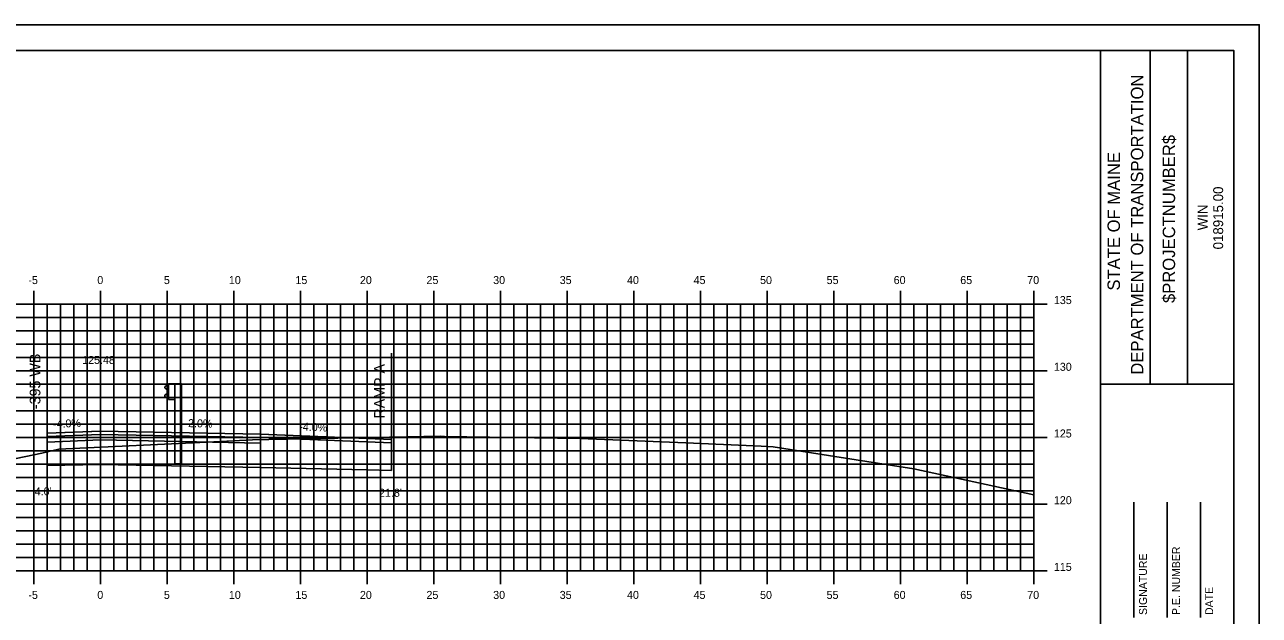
# Model space of a CAD drawing. Extents: x 851960 to 852132, y 365624 to 365734.
# Drawn here: x 852037.6 to 852130.2, y 365689.7 to 365734 of the extents above; entities that cross this region are included whole.
import ezdxf

# ---------------------------------------------------------------- set-up
doc = ezdxf.new("R2010")
doc.units = 0
for name, color, linetype in [('ANNOTATION', 7, 'Continuous'), ('BORDER', 7, 'Continuous'), ('D_Roadway_Centerline', 7, 'Continuous'), ('D_Roadway_Centerline_Text', 7, 'Continuous'), ('D_Roadway_Edge_Shoulder', 7, 'Continuous'), ('D_Roadway_Edge_TW', 7, 'Continuous'), ('D_Roadway_FinishedGrade', 7, 'Continuous'), ('D_Roadway_Pavement', 7, 'Continuous'), ('D_Roadway_SubGrade', 7, 'Continuous'), ('D_Text_Standard', 7, 'Continuous'), ('Default', 7, 'Continuous'), ('H_V ANNOTATION', 7, 'Continuous'), ('M_Guardrail', 7, 'Continuous'), ('M_Roadway_Centerline', 7, 'Continuous'), ('MAJOR', 7, 'Continuous'), ('MINOR', 7, 'Continuous'), ('PLOT BOUNDARY', 7, 'Continuous'), ('S_Roadway_Centerline', 7, 'Continuous')]:
    doc.layers.add(name, color=color, linetype=linetype)

msp = doc.modelspace()

# ---------------------------------------------------------------- linework, layer by layer
at = {"layer": 'BORDER'}
for p, q in [((852118.279, 365627.027), (852118.279, 365732.027)), ((852122.008, 365707.024), (852122.008, 365732.024)), ((852124.803, 365707.024), (852124.803, 365732.024)), ((852118.28, 365707.021), (852128.279, 365707.021)), ((852120.779, 365689.53), (852120.779, 365698.177)), ((852123.279, 365689.53), (852123.279, 365698.177)), ((852125.779, 365689.53), (852125.779, 365698.177))]:
    msp.add_line(p, q, dxfattribs=at)
msp.add_lwpolyline([(851968.279, 365627.027), (852128.279, 365627.027), (852128.279, 365732.027), (851968.279, 365732.027)], close=True, dxfattribs=at)
at = {"layer": 'D_Roadway_Centerline'}
for p, q in [((852063.278, 365702.947), (852065.108, 365702.874)), ((852063.278, 365702.697), (852065.107, 365702.624)), ((852063.278, 365700.607), (852065.107, 365700.544))]:
    msp.add_line(p, q, dxfattribs=at)
msp.add_lwpolyline([(852039.278, 365703.347), (852041.29, 365703.427), (852043.279, 365703.507), (852055.277, 365703.267), (852055.279, 365703.267), (852060.156, 365703.072), (852063.278, 365702.947)], dxfattribs=at)
at = {"layer": 'D_Roadway_Edge_Shoulder'}
for points in [[(852043.279, 365703.507), (852039.278, 365703.347), (852039.278, 365703.097), (852043.279, 365703.257)], [(852055.279, 365703.267), (852063.278, 365702.947), (852063.278, 365702.697), (852055.279, 365703.027)]]:
    msp.add_lwpolyline(points, close=True, dxfattribs=at)
at = {"layer": 'D_Roadway_Edge_TW'}
msp.add_lwpolyline([(852043.279, 365703.507), (852055.279, 365703.267), (852055.279, 365703.027), (852043.279, 365703.257)], close=True, dxfattribs=at)
msp.add_lwpolyline([(852055.279, 365703.267), (852055.279, 365703.101)], dxfattribs=at)
at = {"layer": 'D_Roadway_FinishedGrade'}
for p, q in [((852039.278, 365703.347), (852039.278, 365703.097)), ((852043.279, 365703.507), (852043.279, 365703.257)), ((852055.279, 365703.267), (852055.279, 365703.017)), ((852063.278, 365702.947), (852063.278, 365702.697)), ((852065.107, 365702.859), (852065.107, 365702.609))]:
    msp.add_line(p, q, dxfattribs=at)
at = {"layer": 'D_Roadway_Pavement'}
for points in [[(852043.279, 365703.257), (852039.278, 365703.097), (852039.278, 365702.681), (852043.279, 365702.841)], [(852043.279, 365703.257), (852055.279, 365703.027), (852055.279, 365702.601), (852043.279, 365702.841)]]:
    msp.add_lwpolyline(points, close=True, dxfattribs=at)
msp.add_lwpolyline([(852055.279, 365703.101), (852055.279, 365702.601)], dxfattribs=at)
msp.add_lwpolyline([(852055.279, 365703.101), (852055.279, 365702.601)], dxfattribs=at)
at = {"layer": 'D_Roadway_SubGrade'}
for p, q in [((852039.278, 365709.844), (852039.278, 365700.927)), ((852065.107, 365709.356), (852065.107, 365700.544))]:
    msp.add_line(p, q, dxfattribs=at)
for points in [[(852043.279, 365702.841), (852039.278, 365702.681), (852039.278, 365703.181), (852039.278, 365703.347), (852039.278, 365700.927), (852043.279, 365701.007)], [(852043.279, 365702.841), (852055.279, 365702.601), (852055.279, 365700.767), (852043.279, 365701.007)], [(852055.279, 365702.601), (852055.279, 365703.027), (852063.278, 365702.697), (852063.278, 365702.947), (852063.278, 365700.607), (852055.279, 365700.767)]]:
    msp.add_lwpolyline(points, close=True, dxfattribs=at)
for points in [[(852055.279, 365702.601), (852055.279, 365700.767)], [(852065.107, 365702.609), (852065.107, 365700.544)]]:
    msp.add_lwpolyline(points, dxfattribs=at)
at = {"layer": 'Default'}
msp.add_lwpolyline([(852065.107, 365700.544), (852063.278, 365700.607)], dxfattribs=at)
at = {"layer": 'M_Guardrail'}
for p, q in [((852048.273, 365706.959), (852048.129, 365706.859)), ((852048.129, 365706.716), (852048.325, 365706.58)), ((852048.371, 365706.98), (852048.289, 365706.966)), ((852048.358, 365706.516), (852048.358, 365706.425)), ((852048.371, 365707.053), (852048.861, 365707.053)), ((852048.371, 365705.887), (852048.371, 365707.053)), ((852048.861, 365707.053), (852049.353, 365707.053)), ((852048.861, 365707.053), (852048.861, 365705.887)), ((852049.353, 365707.053), (852049.353, 365701.053)), ((852048.325, 365706.36), (852048.129, 365706.224)), ((852048.129, 365706.081), (852048.273, 365705.981)), ((852048.289, 365705.974), (852048.371, 365705.96)), ((852048.861, 365705.887), (852048.371, 365705.887)), ((852048.861, 365701.053), (852048.861, 365705.887)), ((852048.861, 365701.053), (852049.353, 365701.053))]:
    msp.add_line(p, q, dxfattribs=at)
for centre, major_axis, start_param, end_param in [((852048.18, 365706.788), (-0.0877, 0), 5.323254, 7.243116), ((852048.297, 365706.925), (-0.0417, 0), 4.886922, 5.323254), ((852048.279, 365706.516), (0.0789, 0), 0, 0.959931), ((852048.279, 365706.425), (0.0789, 0), 5.323254, 6.283185), ((852048.18, 365706.152), (-0.0877, 0), 5.323254, 7.243116), ((852048.297, 365706.015), (-0.0417, 0), 0.959931, 1.396263)]:
    msp.add_ellipse(centre, major_axis=major_axis, ratio=0.995501, start_param=start_param, end_param=end_param, dxfattribs=at)
at = {"layer": 'MAJOR'}
for p, q in [((852038.279, 365714.029), (852038.279, 365713.027)), ((852043.279, 365714.029), (852043.279, 365713.027)), ((852048.279, 365714.029), (852048.279, 365713.027)), ((852053.279, 365714.029), (852053.279, 365713.027)), ((852058.279, 365714.029), (852058.279, 365713.027)), ((852063.279, 365714.029), (852063.279, 365713.027)), ((852068.279, 365714.029), (852068.279, 365713.027)), ((852073.279, 365714.029), (852073.279, 365713.027)), ((852078.279, 365714.029), (852078.279, 365713.027)), ((852083.279, 365714.029), (852083.279, 365713.027)), ((852088.279, 365714.029), (852088.279, 365713.027)), ((852093.279, 365714.029), (852093.279, 365713.027)), ((852098.279, 365714.029), (852098.279, 365713.027)), ((852103.279, 365714.029), (852103.279, 365713.027)), ((852108.279, 365714.029), (852108.279, 365713.027)), ((852113.279, 365714.029), (852113.279, 365713.027)), ((851973.279, 365713.027), (852113.279, 365713.027)), ((851973.279, 365713.027), (852113.279, 365713.027)), ((852038.279, 365693.027), (852038.279, 365713.027)), ((852043.279, 365693.027), (852043.279, 365713.027)), ((852048.279, 365693.027), (852048.279, 365713.027)), ((852053.279, 365693.027), (852053.279, 365713.027)), ((852058.279, 365693.027), (852058.279, 365713.027)), ((852063.279, 365693.027), (852063.279, 365713.027)), ((852068.279, 365693.027), (852068.279, 365713.027)), ((852073.279, 365693.027), (852073.279, 365713.027)), ((852078.279, 365693.027), (852078.279, 365713.027)), ((852083.279, 365693.027), (852083.279, 365713.027)), ((852088.279, 365693.027), (852088.279, 365713.027)), ((852093.279, 365693.027), (852093.279, 365713.027)), ((852098.279, 365693.027), (852098.279, 365713.027)), ((852103.279, 365693.027), (852103.279, 365713.027)), ((852108.279, 365693.027), (852108.279, 365713.027)), ((852114.281, 365713.027), (852112.277, 365713.027)), ((852113.279, 365693.027), (852113.279, 365713.027)), ((852113.279, 365693.027), (852113.279, 365713.027)), ((851973.279, 365708.027), (852113.279, 365708.027)), ((852114.281, 365708.027), (852112.277, 365708.027)), ((851973.279, 365703.027), (852113.279, 365703.027)), ((852114.281, 365703.027), (852112.277, 365703.027)), ((851973.279, 365698.027), (852113.279, 365698.027)), ((852114.281, 365698.027), (852112.277, 365698.027)), ((851973.279, 365693.027), (852113.279, 365693.027)), ((851973.279, 365693.027), (852113.279, 365693.027)), ((852038.279, 365692.025), (852038.279, 365693.027)), ((852043.279, 365692.025), (852043.279, 365693.027)), ((852048.279, 365692.025), (852048.279, 365693.027)), ((852053.279, 365692.025), (852053.279, 365693.027)), ((852058.279, 365692.025), (852058.279, 365693.027)), ((852063.279, 365692.025), (852063.279, 365693.027)), ((852068.279, 365692.025), (852068.279, 365693.027)), ((852073.279, 365692.025), (852073.279, 365693.027)), ((852078.279, 365692.025), (852078.279, 365693.027)), ((852083.279, 365692.025), (852083.279, 365693.027)), ((852088.279, 365692.025), (852088.279, 365693.027)), ((852093.279, 365692.025), (852093.279, 365693.027)), ((852098.279, 365692.025), (852098.279, 365693.027)), ((852103.279, 365692.025), (852103.279, 365693.027)), ((852108.279, 365692.025), (852108.279, 365693.027)), ((852114.281, 365693.027), (852112.277, 365693.027)), ((852113.279, 365692.025), (852113.279, 365693.027))]:
    msp.add_line(p, q, dxfattribs=at)
at = {"layer": 'MINOR'}
for p, q in [((852039.279, 365693.027), (852039.279, 365713.027)), ((852040.279, 365693.027), (852040.279, 365713.027)), ((852041.279, 365693.027), (852041.279, 365713.027)), ((852042.279, 365693.027), (852042.279, 365713.027)), ((852044.279, 365693.027), (852044.279, 365713.027)), ((852045.279, 365693.027), (852045.279, 365713.027)), ((852046.279, 365693.027), (852046.279, 365713.027)), ((852047.279, 365693.027), (852047.279, 365713.027)), ((852049.279, 365693.027), (852049.279, 365713.027)), ((852050.279, 365693.027), (852050.279, 365713.027)), ((852051.279, 365693.027), (852051.279, 365713.027)), ((852052.279, 365693.027), (852052.279, 365713.027)), ((852054.279, 365693.027), (852054.279, 365713.027)), ((852055.279, 365693.027), (852055.279, 365713.027)), ((852056.279, 365693.027), (852056.279, 365713.027)), ((852057.279, 365693.027), (852057.279, 365713.027)), ((852059.279, 365693.027), (852059.279, 365713.027)), ((852060.279, 365693.027), (852060.279, 365713.027)), ((852061.279, 365693.027), (852061.279, 365713.027)), ((852062.279, 365693.027), (852062.279, 365713.027)), ((852064.279, 365693.027), (852064.279, 365713.027)), ((852065.279, 365693.027), (852065.279, 365713.027)), ((852066.279, 365693.027), (852066.279, 365713.027)), ((852067.279, 365693.027), (852067.279, 365713.027)), ((852069.279, 365693.027), (852069.279, 365713.027)), ((852070.279, 365693.027), (852070.279, 365713.027)), ((852071.279, 365693.027), (852071.279, 365713.027)), ((852072.279, 365693.027), (852072.279, 365713.027)), ((852074.279, 365693.027), (852074.279, 365713.027)), ((852075.279, 365693.027), (852075.279, 365713.027)), ((852076.279, 365693.027), (852076.279, 365713.027)), ((852077.279, 365693.027), (852077.279, 365713.027)), ((852079.279, 365693.027), (852079.279, 365713.027)), ((852080.279, 365693.027), (852080.279, 365713.027)), ((852081.279, 365693.027), (852081.279, 365713.027)), ((852082.279, 365693.027), (852082.279, 365713.027)), ((852084.279, 365693.027), (852084.279, 365713.027)), ((852085.279, 365693.027), (852085.279, 365713.027)), ((852086.279, 365693.027), (852086.279, 365713.027)), ((852087.279, 365693.027), (852087.279, 365713.027)), ((852089.279, 365693.027), (852089.279, 365713.027)), ((852090.279, 365693.027), (852090.279, 365713.027)), ((852091.279, 365693.027), (852091.279, 365713.027)), ((852092.279, 365693.027), (852092.279, 365713.027)), ((852094.279, 365693.027), (852094.279, 365713.027)), ((852095.279, 365693.027), (852095.279, 365713.027)), ((852096.279, 365693.027), (852096.279, 365713.027)), ((852097.279, 365693.027), (852097.279, 365713.027)), ((852099.279, 365693.027), (852099.279, 365713.027)), ((852100.279, 365693.027), (852100.279, 365713.027)), ((852101.279, 365693.027), (852101.279, 365713.027)), ((852102.279, 365693.027), (852102.279, 365713.027)), ((852104.279, 365693.027), (852104.279, 365713.027)), ((852105.279, 365693.027), (852105.279, 365713.027)), ((852106.279, 365693.027), (852106.279, 365713.027)), ((852107.279, 365693.027), (852107.279, 365713.027)), ((852109.279, 365693.027), (852109.279, 365713.027)), ((852110.279, 365693.027), (852110.279, 365713.027)), ((852111.279, 365693.027), (852111.279, 365713.027)), ((852112.279, 365693.027), (852112.279, 365713.027)), ((851973.279, 365712.027), (852113.279, 365712.027)), ((852113.279, 365712.027), (852112.277, 365712.027)), ((851973.279, 365711.027), (852113.279, 365711.027)), ((852113.279, 365711.027), (852112.277, 365711.027)), ((851973.279, 365710.027), (852113.279, 365710.027)), ((852113.279, 365710.027), (852112.277, 365710.027)), ((851973.279, 365709.027), (852113.279, 365709.027)), ((852113.279, 365709.027), (852112.277, 365709.027)), ((851973.279, 365707.027), (852113.279, 365707.027)), ((852113.279, 365707.027), (852112.277, 365707.027)), ((851973.279, 365706.027), (852113.279, 365706.027)), ((852113.279, 365706.027), (852112.277, 365706.027)), ((851973.279, 365705.027), (852113.279, 365705.027)), ((852113.279, 365705.027), (852112.277, 365705.027)), ((851973.279, 365704.027), (852113.279, 365704.027)), ((852113.279, 365704.027), (852112.277, 365704.027)), ((851973.279, 365702.027), (852113.279, 365702.027)), ((852113.279, 365702.027), (852112.277, 365702.027)), ((851973.279, 365701.027), (852113.279, 365701.027)), ((852113.279, 365701.027), (852112.277, 365701.027)), ((851973.279, 365700.027), (852113.279, 365700.027)), ((852113.279, 365700.027), (852112.277, 365700.027)), ((851973.279, 365699.027), (852113.279, 365699.027)), ((852113.279, 365699.027), (852112.277, 365699.027)), ((851973.279, 365697.027), (852113.279, 365697.027)), ((852113.279, 365697.027), (852112.277, 365697.027)), ((851973.279, 365696.027), (852113.279, 365696.027)), ((852113.279, 365696.027), (852112.277, 365696.027)), ((851973.279, 365695.027), (852113.279, 365695.027)), ((852113.279, 365695.027), (852112.277, 365695.027)), ((851973.279, 365694.027), (852113.279, 365694.027)), ((852113.279, 365694.027), (852112.277, 365694.027))]:
    msp.add_line(p, q, dxfattribs=at)
at = {"layer": 'PLOT BOUNDARY'}
msp.add_lwpolyline([(851960.186, 365623.968), (852130.186, 365623.968), (852130.186, 365733.968), (851960.186, 365733.968)], close=True, dxfattribs=at)
at = {"layer": 'S_Roadway_Centerline'}
msp.add_lwpolyline([(852034.395, 365700.928), (852038.877, 365701.862), (852040.156, 365702.14), (852051.771, 365702.708), (852054.685, 365702.852), (852055.904, 365702.884), (852066.247, 365703.068), (852068.777, 365703.117), (852069.083, 365703.094), (852074.124, 365703.032), (852079.246, 365702.952), (852087.176, 365702.618), (852092.829, 365702.365), (852093.737, 365702.318), (852099.152, 365701.481), (852104.273, 365700.683), (852113.279, 365698.723)], dxfattribs=at)

# ---------------------------------------------------------------- texts
at = {"layer": 'ANNOTATION'}
for s, height, rotation, p in [('I-395 WB', 0.8, 90, (852038.771, 365704.854)), ('RAMP A', 0.8, 90, (852064.6, 365704.44)), ('-4.0%', 0.6, 2.29045, (852039.724, 365703.74)), ('-2.0%', 0.6, 358.85424, (852049.575, 365703.81)), ('-4.0%', 0.6, 357.70931, (852058.174, 365703.552))]:
    msp.add_text(s, height=height, rotation=rotation, dxfattribs=at).set_placement(p)
at = {"layer": 'BORDER'}
for s, height, p in [('DEPARTMENT OF TRANSPORTATION', 0.93176, (852121.486, 365707.733)), ('$PROJECTNUMBER$', 0.93176, (852123.871, 365713.106)), ('STATE OF MAINE', 0.93176, (852119.734, 365714.039)), ('018915.00', 0.7453, (852127.474, 365717.125)), ('WIN', 0.7453, (852126.316, 365718.557)), ('P.E. NUMBER', 0.59055, (852124.24, 365689.722)), ('SIGNATURE', 0.5906, (852121.759, 365689.722)), ('DATE', 0.5906, (852126.72, 365689.722))]:
    msp.add_text(s, height=height, rotation=90, dxfattribs=at).set_placement(p)
at = {"layer": 'D_Roadway_Centerline'}
for s, p in [('C', (852043.273, 365703.507)), ('L', (852043.279, 365703.499))]:
    msp.add_text(s, height=0.0146, dxfattribs=at).set_placement(p)
at = {"layer": 'D_Roadway_Centerline_Text'}
msp.add_text('125.48', height=0.6, dxfattribs=at).set_placement((852041.901, 365708.539))
at = {"layer": 'D_Text_Standard'}
for s, p in [("4.0'", (852038.345, 365698.693)), ("21.8'", (852064.168, 365698.583))]:
    msp.add_text(s, height=0.6, dxfattribs=at).set_placement(p)
at = {"layer": 'H_V ANNOTATION'}
for s, p in [('-5', (852037.869, 365714.527)), ('0', (852043.038, 365714.527)), ('5', (852048.03, 365714.527)), ('10', (852052.904, 365714.527)), ('15', (852057.896, 365714.527)), ('20', (852062.733, 365714.527)), ('25', (852067.725, 365714.527)), ('30', (852072.727, 365714.527)), ('35', (852077.719, 365714.527)), ('40', (852082.765, 365714.527)), ('45', (852087.757, 365714.527)), ('50', (852092.743, 365714.527)), ('55', (852097.735, 365714.527)), ('60', (852102.765, 365714.527)), ('65', (852107.757, 365714.527)), ('70', (852112.781, 365714.527)), ('135', (852114.779, 365713.027)), ('130', (852114.779, 365708.027)), ('125', (852114.779, 365703.027)), ('120', (852114.779, 365698.027)), ('115', (852114.779, 365693.027)), ('-5', (852037.869, 365690.927)), ('0', (852043.038, 365690.927)), ('5', (852048.03, 365690.927)), ('10', (852052.904, 365690.927)), ('15', (852057.896, 365690.927)), ('20', (852062.733, 365690.927)), ('25', (852067.725, 365690.927)), ('30', (852072.727, 365690.927)), ('35', (852077.719, 365690.927)), ('40', (852082.765, 365690.927)), ('45', (852087.757, 365690.927)), ('50', (852092.743, 365690.927)), ('55', (852097.735, 365690.927)), ('60', (852102.765, 365690.927)), ('65', (852107.757, 365690.927)), ('70', (852112.781, 365690.927))]:
    msp.add_text(s, height=0.6, dxfattribs=at).set_placement(p)
at = {"layer": 'M_Roadway_Centerline'}
for s, p in [('C', (852068.772, 365703.117)), ('L', (852068.777, 365703.11))]:
    msp.add_text(s, height=0.0146, dxfattribs=at).set_placement(p)

doc.saveas('drawing.dxf')
